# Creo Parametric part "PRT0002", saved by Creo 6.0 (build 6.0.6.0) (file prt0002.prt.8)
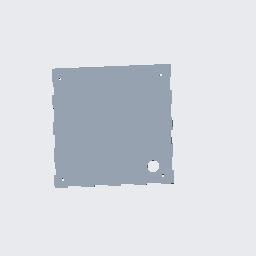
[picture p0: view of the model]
Units: Inch lbm Second (Pro/E Default); INCH, POUND, SECS

Created from: INLBS_PART_SOLID.PRT

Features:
  1. datum plane "RIGHT"
  2. datum plane "TOP"
  3. datum plane "FRONT"
  4. coordinate system
  5. sketch "Sketch 1"
  6. extrusion "Extrude 1"
  7. sketch "Sketch 2"
  8. extruded cut "Extrude 2"
  9. sketch "Sketch 3"
  10. sketch "Sketch 4"
  11. sketch "Sketch 5"
  12. extruded cut "Extrude 3"

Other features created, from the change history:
  extruded cut "Extrude 3" (2 times)
  sketch "Sketch 4"

Surfaces: 54 plane, 5 cylinder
